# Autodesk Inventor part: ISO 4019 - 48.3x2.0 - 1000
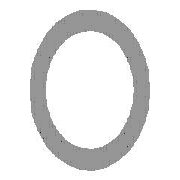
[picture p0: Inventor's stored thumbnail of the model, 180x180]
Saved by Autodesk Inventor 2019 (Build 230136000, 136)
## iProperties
IsCustomPart: 1
Created: 2018-01
Part Number: ISO 4019 - 48.3x2.0 - 1000
Material: Acier, doux
Description: Aciers de construction - Coupes creuses profilées formées à froid, soudées
Document SubType Name: Modeling
Standard: ISO
Designer: Fabian Perrée
Standard Revision: Second edition 2001-09-01
Standards Organization: ISO
Language: fr-FR
Size Designation: 48.3x2.0
Categories: <MemberInstance><Categories><Category DisplayName="Profilés" InternalName="089c4875-fa83-4c05-b084-43b9cc11f5ed" Mnemonic="GRDR"><CategoryParameter DisplayName=
Stock Number: 48.3x2.0
Density: 7.85 g/cm^3
Appearance: Semi-poli
Mass: 2169.32 g
Surface Area: 2784.02 cm^2
Volume: 276.347 cm^3
_CCFamilyMember: 14
_CCFamilyDisplayName: ISO 4019 (Profils creux circulaires - Formés à froid) - Aciers de construction - Coupes creuses profilées formées à froid, soudées — ISO 4019 (Profils creux cir
_FrameMemberDoc: Frame Member File
_Version: 15.0.0
_GetPNFromCC: 1
G_L: 1000,000 mm
G_W: 48,300 mm
G_H: 48,300 mm
+6CF9212D-CCC1-49D6-9294-5D3E9515860C+DETAILDECOUPE1: Grugeage
+010BC43A-D804-4444-9BAD-6047175C2C4F+DETAILDECOUPE2: Grugeage
Author: Fabian Perrée
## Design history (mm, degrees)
node "Plan de départ"
node "Plan de fin"
sketch "Esquisse"
  geometry: C1 r 22.15 at (0, 0); C2 r 24.15 at (0, 0); 2 further points
  constraints: 3 coincident, 2 centre point
  dimensions: "d0" = 48.3 diameter of C2 (= G_H); "d1" = 2 radial gap between concentric circles of C2 C1 (= G_T)
extrude "Corps" new body sketch "Esquisse" stored distance "d2" = 1000 (= G_L); taper "d3" = 0 deg
node "Driven Length"
  sketch "Sketch3"
    geometry: L1 (0, 0)-(10, 0) reference
    constraints: 2 end point, 1 horizontal
  workplane "Work Plane3"
  sketch "Sketch4"
    geometry: L1 (-2, 0)-(12, 0) reference; L2 (-2, 1000)-(12, 1000) reference
    dimensions: "d7" = 1000 distance between parallel lines of L1 L2 (derived)
body "Solid1"
feature "Sculpter1"
feature "Combiner1"
feature "Sculpter3"
feature "Combiner3"
body "Srf14"
body "Srf15"
node "Solide6"
body "Srf17"
body "Srf18"
node "Solide7"
feature "Surface1"
body "Srf13"
feature "Carreau délimité9" dims "d24" = 5, "d25" = 0
feature "Carreau délimité10" dims "d26" = 5, "d27" = 0
feature "Surface3"
body "Srf16"
feature "Carreau délimité11" dims "d28" = 5, "d29" = 0
feature "Carreau délimité12" dims "d30" = 5, "d31" = 0
other parameters: "G_H" = 48.3 [user parameter; used in 1 equation term], "G_T" = 2 [user parameter; used in 1 equation term], "G_L" = 1000 (= d7) [user parameter; used in 1 equation term], "G_OFFSET_START" = 0 [user parameter; used in 1 equation term], "G_OFFSET_END" = 0 [user parameter; used in 1 equation term], "d4" = 0 (computed from G_OFFSET_START), "d6" = 90 deg, "MAS" = 0.228 [user parameter]
